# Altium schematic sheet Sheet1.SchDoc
size 420 x 297 mm; SheetNumber: 1; SheetTotal: 1
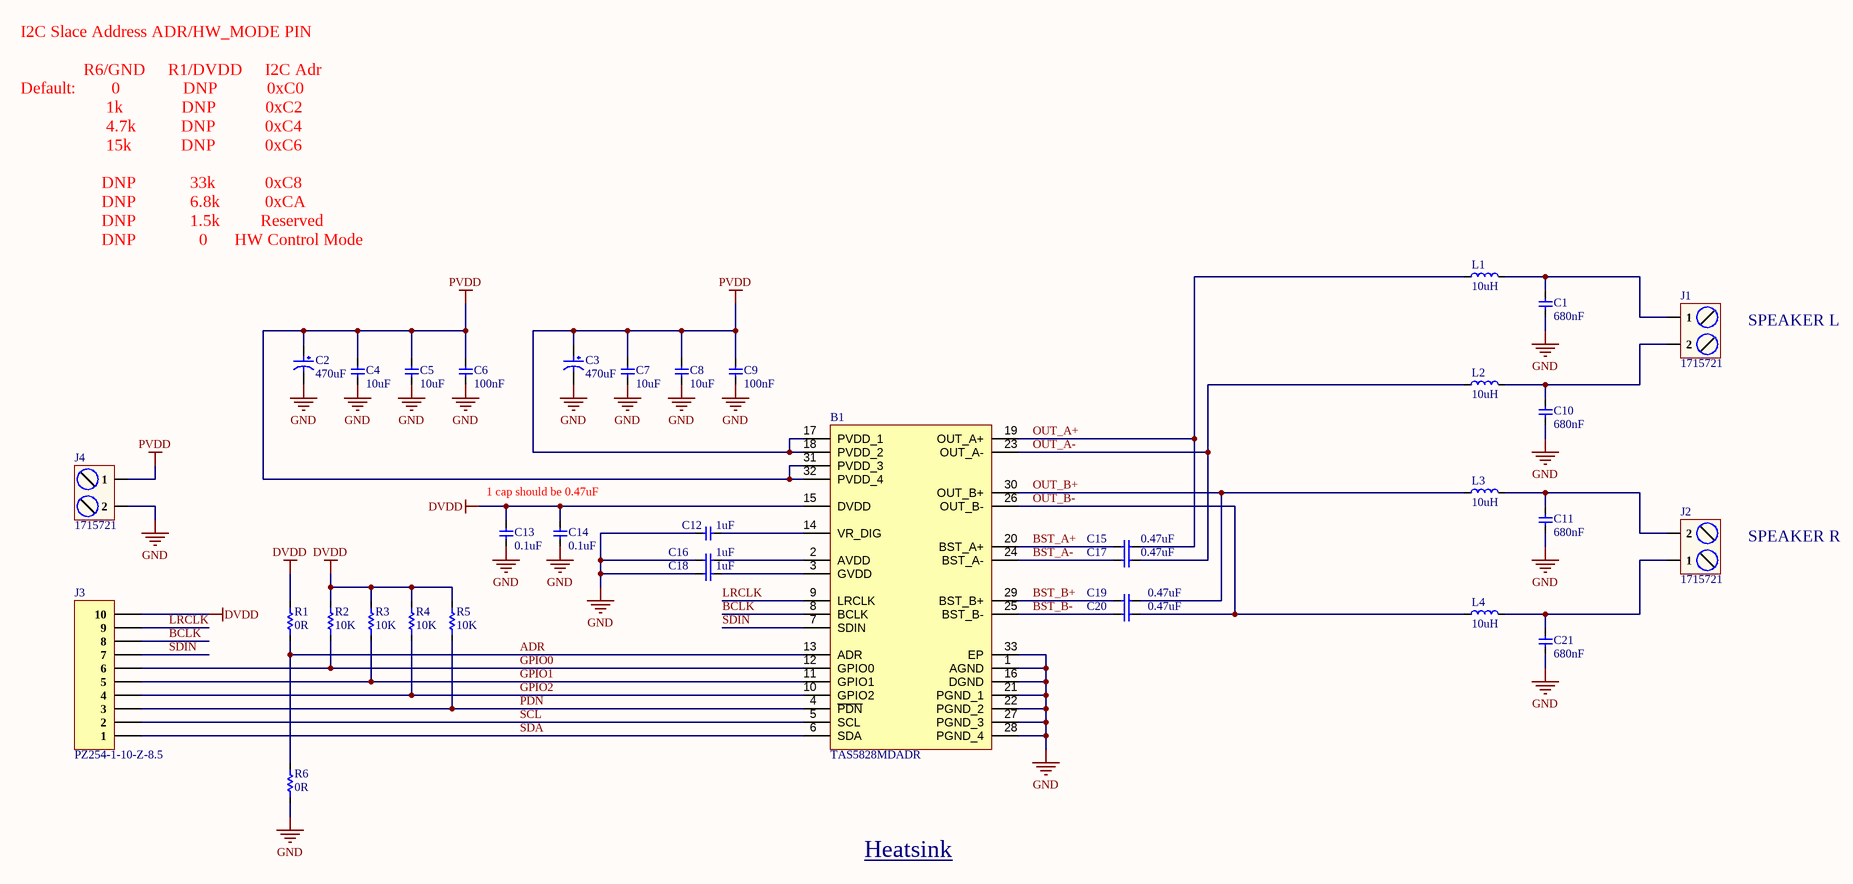
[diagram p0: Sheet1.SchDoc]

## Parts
B1  TAS5828MDADR  [SOP65P810X115-33M]
C1  680nF  [Cap-0805]
C2  470uF  [RVT470UF50V34RV0133]
C3  470uF  [RVT470UF50V34RV0133]
C4  10uF  [Cap-0805]
C5  10uF  [Cap-0805]
C6  100nF  [Cap-0603]
C7  10uF  [Cap-0805]
C8  10uF  [Cap-0805]
C9  100nF  [Cap-0603]
C10  680nF  [Cap-0805]
C11  680nF  [Cap-0805]
C12  1uF  [Cap-0603]
C13  0.1uF  [Cap-0402]
C14  0.1uF  [Cap-0402]
C15  0.47uF  [Cap-0603]
C16  1uF  [Cap-0603]
C17  0.47uF  [Cap-0603]
C18  1uF  [Cap-0603]
C19  0.47uF  [Cap-0603]
C20  0.47uF  [Cap-0603]
C21  680nF  [Cap-0805]
J1  1715721  [1715721]
J2  1715721  [1715721]
J3  PZ254-1-10-Z-8.5  [PZ254-1-10-Z-8.5]
J4  1715721  [1715721]
L1  10uH  [PSPMAA1040-100M-ANP]
L2  10uH  [PSPMAA1040-100M-ANP]
L3  10uH  [PSPMAA1040-100M-ANP]
L4  10uH  [PSPMAA1040-100M-ANP]
R1  0R  [Res-0402]
R2  10K  [Res-0402]
R3  10K  [Res-0402]
R4  10K  [Res-0402]
R5  10K  [Res-0402]
R6  0R  [Res-0402]

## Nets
DVDD: B1.15(DVDD) C13.2 C14.2 J3.10 R1.2 R2.2 R3.2 R4.2 R5.2
GND: B1.1(AGND) B1.16(DGND) B1.21(PGND_1) B1.22(PGND_2) B1.27(PGND_3) B1.28(PGND_4) B1.33(EP) C1.1 C2.2 C3.2 C4.1 C5.1 C6.1 C7.1 C8.1 C9.1 C10.1 C11.1 C12.1 C13.1 C14.1 C16.1 C18.1 C21.1 J4.2 R6.1
PVDD: B1.17(PVDD_1) B1.18(PVDD_2) B1.31(PVDD_3) B1.32(PVDD_4) C2.1 C3.1 C4.2 C5.2 C6.2 C7.2 C8.2 C9.2 J4.1
ADR: B1.13(ADR) R1.1 R6.2
BCLK: B1.8(BCLK) J3.8
BST_A+: B1.20(BST_A+) C15.1
BST_A-: B1.24(BST_A-) C17.1
BST_B+: B1.29(BST_B+) C19.1
BST_B-: B1.25(BST_B-) C20.1
GPIO0: B1.12(GPIO0) J3.6 R2.1
GPIO1: B1.11(GPIO1) J3.5 R3.1
GPIO2: B1.10(GPIO2) J3.4 R4.1
LRCLK: B1.9(LRCLK) J3.9
OUT_A+: B1.19(OUT_A+) C15.2 L1.1
OUT_A-: B1.23(OUT_A-) C17.2 L2.1
OUT_B+: B1.30(OUT_B+) C19.2 L3.1
OUT_B-: B1.26(OUT_B-) C20.2 L4.1
PDN: B1.4(~{PDN}) J3.3 R5.1
SCL: B1.5(SCL) J3.2
SDA: B1.6(SDA) J3.1
SDIN: B1.7(SDIN) J3.7
NetB1_2: B1.2(AVDD) C16.2
NetB1_3: B1.3(GVDD) C18.2
NetB1_14: B1.14(VR_DIG) C12.2
NetC1_2: C1.2 J1.1 L1.2
NetC10_2: C10.2 J1.2 L2.2
NetC11_2: C11.2 J2.2 L3.2
NetC21_2: C21.2 J2.1 L4.2

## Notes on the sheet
- I2C Slace Address ADR/HW_MODE PIN
  R6/GND     R1/DVDD     I2C Adr
  Default:        0              DNP           0xC0
  1k             DNP           0xC2
  4.7k          DNP           0xC4
  15k           DNP           0xC6
  DNP            33k           0xC8
  DNP            6.8k          0xCA
  DNP            1.5k         Reserved
  DNP              0      HW Control Mode
- SPEAKER L
- 1 cap should be 0.47uF
- SPEAKER R
- Heatsink <https://www.lcsc.com/product-detail/Heat-sink-heatsink_XSD-XSD271-294-B_C286198.html>

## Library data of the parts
B1 = TAS5828MDADR: Audio Amplifiers 50-W stereo, digital input, high-performance, closed-loop, Class-D, with integrated audio processor 32-HTSSOP -40 to 85; Manufacturer_Name: Texas Instruments; Geometry.Height: 1.15mm
C1 C10 C11 C21 = CC0805KKX7R9BB684: 50V 680nF X7R ±10% 0805 Multilayer Ceramic Capacitors MLCC - SMD/SMT ROHS; Manufacturer: YAGEO; Item Type: Cap
C2 C3 = RVT470UF50V34RV0133: 470uF 50V 50mA@120Hz ±20% SMD,D12.5xL13.5mm Aluminum Electrolytic Capacitors - SMD ROHS; Manufacturer: KNSCHA
C4 C5 C7 C8 = GRM21BR61H106ME43L: CAP CER 10UF 50V X5R 0805; Manufacturer: Murata
C6 C9 = CC0603KRX5R9BB104: CAP CER 0.1UF 50V X5R 0603; Manufacturer: Yageo; Tolerance: 10%; Item Type: Capacitor
C12 C16 C18 = CC0603KRX5R8BB105: CAP CER 1UF 25V X5R 0603; Manufacturer: Yageo; Tolerance: 10%; Item Type: Capacitor
C13 C14 = CC0402JRX7R7BB104: CAP CER 0.1UF 16V X7R 0402; Manufacturer: Yageo; Material: 4241ConductorMaterial; Value: 100nF; Tolerance: 5%; Item Type: Capacitor
C15 C17 C19 C20 = CC0603KRX5R9BB474: CAP CER 0.47UF 50V X5R 0603; Manufacturer: Yageo; Capacitance: 470nF; Tolerance: 10%; Item Type: Capacitor
J1 J2 J4 = 1715721: TERM BLK 2P SIDE ENT 5.08MM PCB; Manufacturer: Phoenix Contact; Item Type: Terminal Blocks
J3 = PZ254-1-10-Z-8.5: 3A Direct Insert Policy 2.5mm 260℃@10S 10P 6mm -40℃~+105℃ 3mm 2.54mm Single Row Black Brass 1x10P Plugin,P=2.54mm Pin Headers ROHS; Manufacturer: HCTL; Item Type: Header
L1-L4 = PSPMAA1040-100M-ANP: 7A 10uH ±20% 10A SMD,10.3x10.5mm Power Inductors ROHS; Manufacturer: PROD Tech
R1 R6 = RC0402FR-070RL: RES 0 OHM JUMPER 1/16W 0402; Manufacturer: Yageo; Item Type: Resistors; Tolerance: 1%; Power Rating: 62.5mW; Voltage Rating: 50V; Temperature Coefficient: 200ppm/°C; Max Power Dissipation: 63mW
R2-R5 = RC0402FR-0710KL: RES 10K OHM 1% 1/16W 0402; Manufacturer: Yageo; Resistance: 10kR; Voltage Rating (DC): 50V; Temperature Coefficient: 100ppm/°C; Power Rating: 62.5mW; Max Power Dissipation: 63mW; Item Type: Resistor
